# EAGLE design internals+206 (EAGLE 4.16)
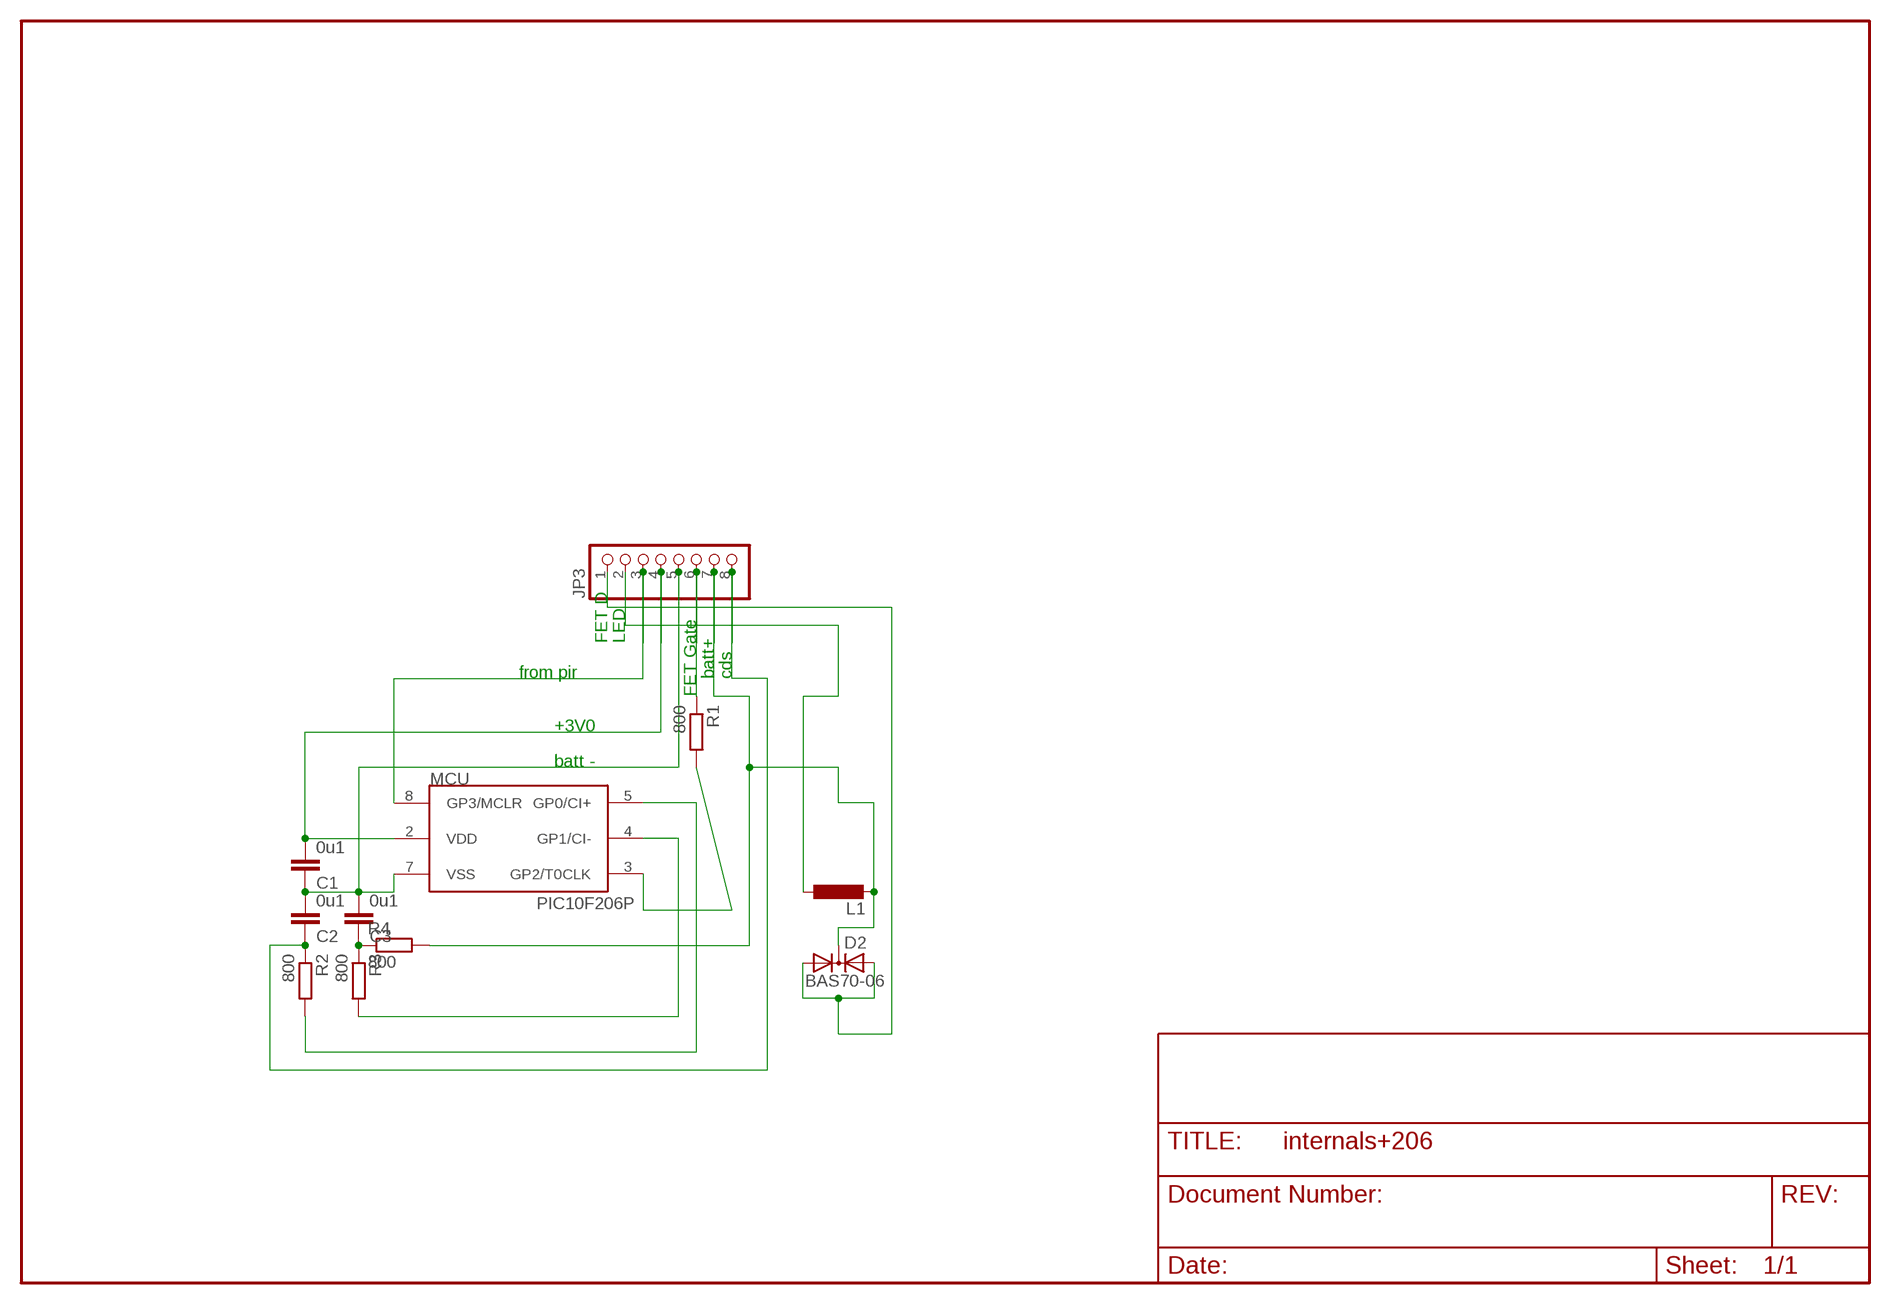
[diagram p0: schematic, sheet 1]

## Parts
C1  0u1  C-EUC1206  [C1206]
C2  0u1  C-EUC1206  [C1206]
C3  0u1  C-EUC1206  [C1206]
D2  BAS70-06  [SOT23]
JP3  PINHD-1X8  [1X08]
L1  L-EU0207/7  [0207/7]
MCU  PIC10F206P  [DIL8]
R1  800  R-EU_R1206  [R1206]
R2  800  R-EU_R1206  [R1206]
R3  800  R-EU_R1206  [R1206]
R4  800  R-EU_R1206  [R1206]

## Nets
N$1: C1.1 C2.2 C3.2 JP3.5 MCU.7(VSS)
N$2: MCU.5(GP0/CI+) R2.2
N$3: D2.3(C) JP3.7 L1.2 R4.2
N$4: MCU.4(GP1/CI-) R3.2
N$5: D2.1(A1) D2.2(A2) JP3.1
N$6: C1.2 JP3.4 MCU.2(VDD)
N$8: JP3.2 L1.1
N$9: JP3.6 R1.1
N$10: C3.1 R3.1 R4.1
N$11: C2.1 JP3.8 R2.1
N$13: JP3.3 MCU.8(GP3/MCLR)
N$14: MCU.3(GP2/T0CLK) R1.2

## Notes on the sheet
- FET D | LED
- from pir | batt+ | cds
- FET Gate
- +3V0
- batt -

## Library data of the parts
C1-C3 = rcl:C-EU: CAPACITOR, European symbol
D2 = diode-1:BAS70-06: Silicon Schottky Diodes General-purpose diode for high-speed switching
JP3 = pinhead(2):PINHD-1X8: PIN HEADER
L1 = rcl:L-EU: INDUCTOR, European symbol
MCU = microchip-3:PIC10F2*: uPC nW 0,25/0,5k Program Flash memory Comparator
R1-R4 = rcl:R-EU_: RESISTOR, European symbol

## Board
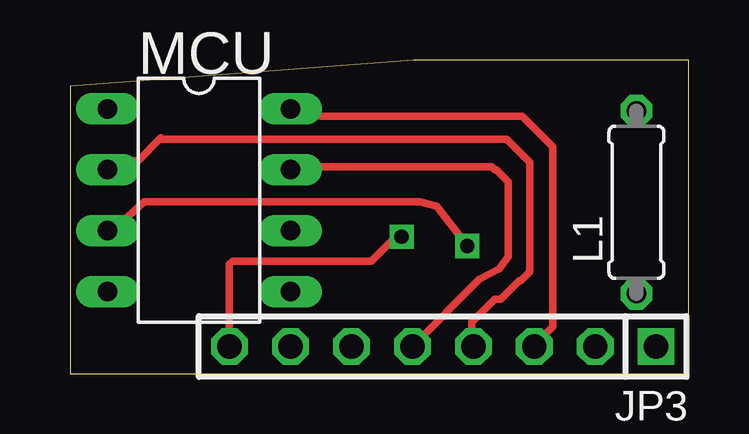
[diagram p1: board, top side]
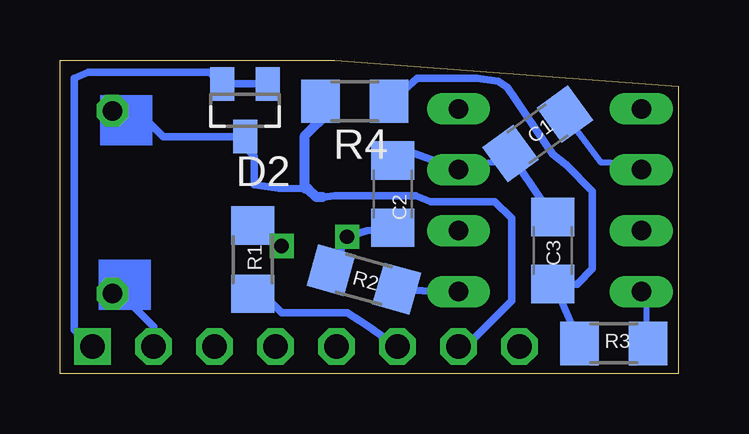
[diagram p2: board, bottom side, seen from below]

Size 25.77 x 13.08 mm. Coordinates in mm from the lower left corner, seen from the top.
Outline: 0,0 25.77,0 25.77,13.07 18,13.07 14.31,13.08 0,11.99 0,0
Copper layers (1*16): Top 0.035mm / dielectric 1.5mm / Bottom 0.035mm
Design rules "default": minimum track width 10mil, minimum drill 24mil, track to track 8mil, track to pad 8mil, pad to pad 8mil, via to via 8mil, smd to smd 8mil, copper to edge 1mil, drill to drill 8mil, minimum pad ring 10mil, minimum via ring 8mil, stop-mask expansion 4mil, vias tented up to drill 0mil, thermal gap 10mil

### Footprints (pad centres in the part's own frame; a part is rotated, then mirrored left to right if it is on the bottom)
C1206 = smd 1.6 x 1.8: 1 -1.4,0; 2 1.4,0
SOT23 = smd 1 x 1.4: 1 -0.95,-1.1; 2 0.95,-1.1; 3 0,1.1
1X08 = drill 1.016 square: 1 -8.89,0 | drill 1.016 octagon: 2 -6.35,0; 3 -3.81,0; 4 -1.27,0; 5 1.27,0; 6 3.81,0; 7 6.35,0; 8 8.89,0
0207/7 = drill 0.813 octagon: 1 -3.81,0; 2 3.81,0
DIL8 = drill 0.813 long: 1 -3.81,-3.81; 2 -1.27,-3.81; 3 1.27,-3.81; 4 3.81,-3.81; 5 3.81,3.81; 6 1.27,3.81; 7 -1.27,3.81; 8 -3.81,3.81
R1206 = smd 1.6 x 1.803: 1 -1.422,0; 2 1.422,0

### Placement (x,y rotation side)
C1  5.87,10 35.9 bottom
C2  11.9,7.49 90 bottom
C3  5.23,5.14 90 bottom
D2  18.06,10.98 180 bottom
JP3  15.52,1.14 180 top
L1  23.59,7.15 90 top
MCU  5.36,7.23 270 top
R1  17.74,4.76 90 bottom
R2  13.11,3.93 344.4 bottom
R3  2.69,1.27 0 bottom
R4  13.49,11.36 180 bottom

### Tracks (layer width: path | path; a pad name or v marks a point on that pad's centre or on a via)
N$1
  Top 0.305: MCU.7 9.23,8.5 9.36,8.63 17.55,8.63 17.68,8.5 17.74,8.5 18.25,8 18.25,4.88 17.87,4.38 17.04,3.93 JP3.5
  Bottom 0.254: C1.1 7.53,8.79 7.93,8.79 MCU.7
  Bottom 0.305: C2.2 11.27,9.27 9.3,8.57 MCU.7 | C1.1 6.95,9.08 C3.2
N$2
  Bottom 0.305: MCU.5 9.3,3.36 R2.2
N$3
  Bottom 0.305: 15.56,7.72 16.66,7.74 17.68,7.87 17.68,9.08 18.06,9.46 D2.3 21.47,9.88 23.01,11.43 L1.2 | JP3.7 8.85,1.14 6.95,3.04 6.95,6.47 7.65,7.17 10.31,7.17 10.95,7.42 14.31,7.42 14.82,7.36 | R4.2 14.91,11.32 14.54,10.95 14.38,10.79
  Bottom 0.406: 14.82,7.36 15.08,7.36 15.44,7.72 15.56,7.72 15.56,9.92 14.54,10.95 | 14.54,10.95
N$4
  Bottom 0.254: R3.2 1.33,2.1 1.33,2.79 MCU.4
N$5
  Bottom 0.305: D2.2 D2.1 | D2.2 19.16,11.7 19.2,11.74 | JP3.1 25.17,1.84 25.17,12.31 24.6,12.57 19.52,12.57 19.03,12.08 D2.2
N$6
  Top 0.305: MCU.2 1.61,8.5 1.99,8.88 2.82,8.88 3.77,9.84 3.84,9.77 18.19,9.77 19.14,8.82 19.14,4.25 18.76,3.87 18.69,3.87 17.93,3.11 17.68,3.11 16.73,2.15 16.73,1.07 JP3.4
  Bottom 0.254: C1.2 3.23,8.79 2.83,8.79 MCU.2
N$8
  Bottom 0.305: L1.1 23.01,3.11 21.87,1.96 21.87,1.2 21.93,1.14 JP3.2
N$9
  Bottom 0.305: JP3.6 12.98,2.03 13.81,2.54 16.54,2.54 17.42,3.42 17.51,3.34 R1.1
N$10
  Bottom 0.305: R4.1 11.96,11.36 10.88,12.31 8.41,12.31 7.52,12.19 7.14,11.93 5.23,9.14 4.66,8.69 3.58,7.62 3.58,4.38 4.22,3.74 C3.1 5.17,3.74 R3.1
N$11  (via drill 0.6)
  Top 0.305: v13.81,5.71 13.55,5.71 12.53,4.69 6.76,4.69 6.63,4.57 6.63,1.2 6.69,1.14 JP3.8
  Bottom 0.305: R2.1 v13.81,5.71 12.98,5.96 C2.1
N$13
  Top 0.305: MCU.8 9.36,11.04 9.42,11.23 10.44,10.73 18.82,10.73 20.09,9.46 20.09,1.96 19.33,1.2 JP3.3
N$14  (via drill 0.6)
  Top 0.305: v16.54,5.33 15.27,6.98 14.57,7.17 3.07,7.17 1.74,5.96 MCU.3
  Bottom 0.305: R1.2 17.77,6.37 v16.54,5.33
(copper drawn outside any net)
  shapes: Bottom area x2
